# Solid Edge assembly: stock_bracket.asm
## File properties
Author: vicky raina
Template: Normal.asm
Last saved by: CADCIM Technologies
Revision: 25
Application: Solid Edge
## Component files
adjusting_screw_guide.par
adjusting_nut_handle.par
stock_support_roller.par
Stock_support_base.par
thrust_bearing.par
adjusting_screw_nut.par
support_adjusting_screw.par
support_roller_bracket.par
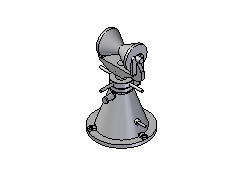
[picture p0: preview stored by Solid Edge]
